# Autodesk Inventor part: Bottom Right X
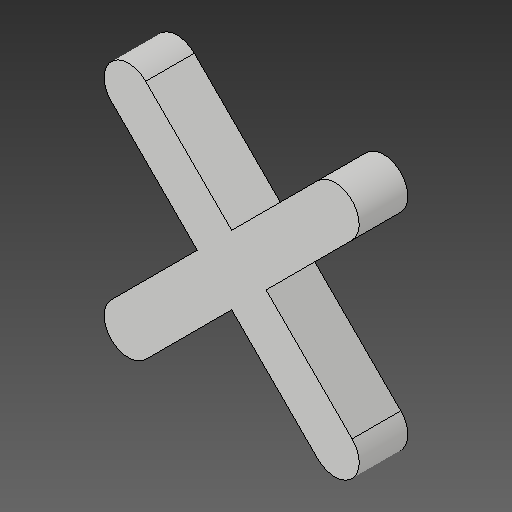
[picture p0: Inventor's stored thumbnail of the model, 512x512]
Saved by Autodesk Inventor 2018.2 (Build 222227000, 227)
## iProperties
Created: 2018-03
Part Number: Bottom Right X
Material: Generic
Document SubType Name: Modeling
Designer: PeterMaxwell-Stewart
Mass: 1.57135 g
Surface Area: 12.8562 cm^2
Volume: 1.57135 cm^3
Density: 1 g/cm^3
Appearance: Default
Author: PeterMaxwell-Stewart
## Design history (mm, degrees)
derived "O's and X's.ipt"
feature "Bottom Right X::O's and X's.ipt" dims "d0" = 10
tag "TaggingFeature1"
body "Solid1"
